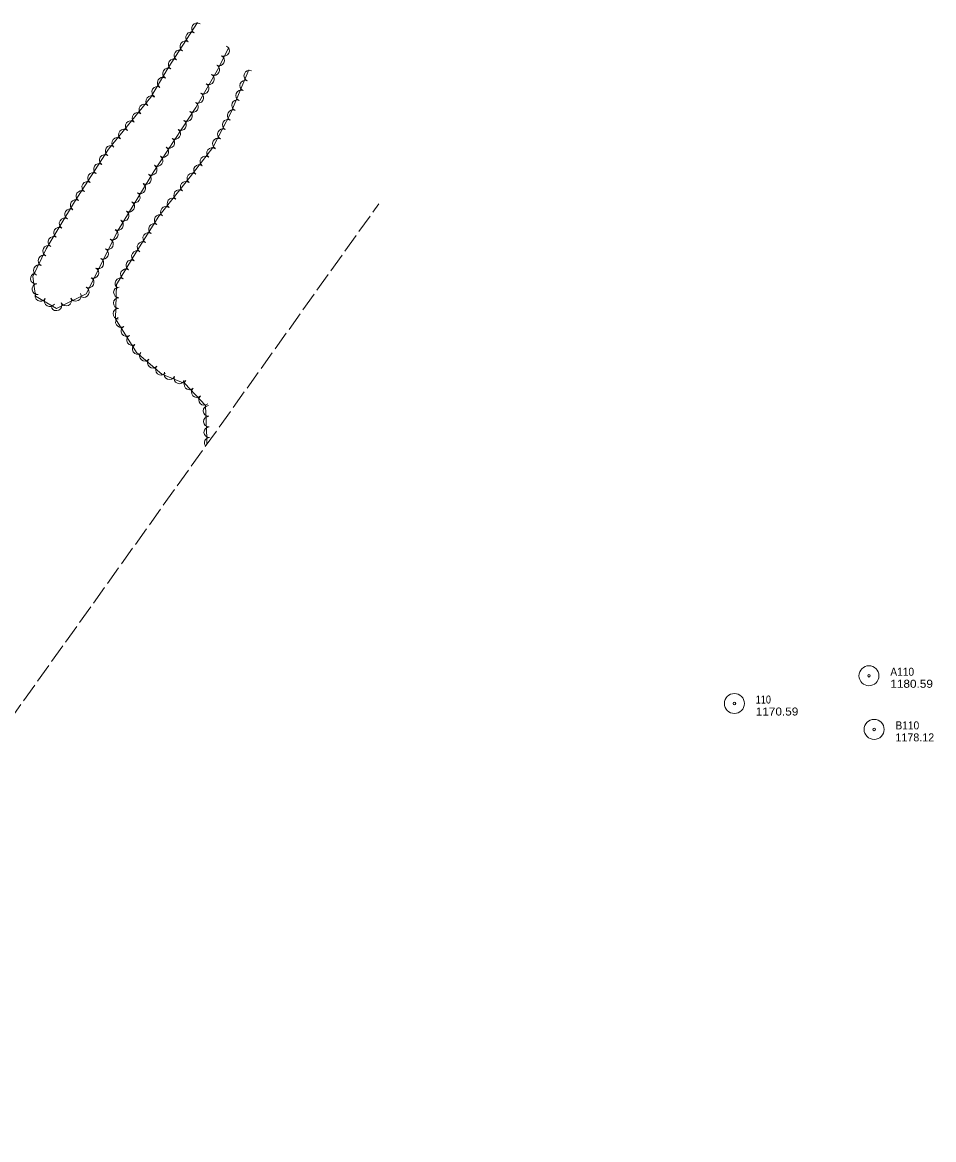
# Model space of a CAD drawing. Extents: x 298072 to 300359, y 47756 to 50122.
# Drawn here: x 299676 to 300359, y 48286 to 49123 of the extents above; entities that cross this region are included whole.
import ezdxf

# ---------------------------------------------------------------- set-up
doc = ezdxf.new("R2010")
doc.units = 0
doc.header["$LTSCALE"] = 2.4
doc.linetypes.add('LONG_DASHED', pattern=[7.5, 6, -1.5])
for name, color, linetype, lineweight in [('18', 7, 'Continuous', 13), ('4', 7, 'Continuous', 13), ('6', 7, 'Continuous', 13)]:
    doc.layers.add(name, color=color, linetype=linetype, lineweight=lineweight)

msp = doc.modelspace()

# ---------------------------------------------------------------- linework, layer by layer
at = {"layer": '18'}
for points in [[(299807.427, 49123.128), (299785.282, 49089.002), (299772.357, 49066.944), (299740.591, 49028.036), (299715.161, 48988.72), (299693.854, 48953.382), (299683.94, 48932.544), (299685.992, 48917.856), (299701.571, 48908.735), (299723.825, 48919.654), (299747.803, 48967.414), (299774.543, 49011.39), (299806.019, 49059.246), (299822.144, 49087.161), (299830.837, 49104.378)], [(299845.727, 49087.598), (299832.328, 49055.349), (299818.687, 49029.29), (299801.791, 49007.312), (299778.25, 48977.779), (299761.263, 48950.809), (299746.548, 48926.585), (299745.914, 48901.043), (299761.679, 48875.802), (299780.701, 48859.42), (299797.834, 48852.383), (299813.404, 48835.916), (299814.228, 48811.396), (299814.385, 48806.967)]]:
    msp.add_lwpolyline(points, dxfattribs=at)
for centre, radius, start, end in [((299807.003, 49118.605), 4.025, 57.02737, 237.01204), ((299798.24, 49105.101), 4.025, 57.02737, 237.01204), ((299802.622, 49111.853), 4.025, 57.02737, 237.01204), ((299793.859, 49098.35), 4.025, 57.02737, 237.01204), ((299827.143, 49101.735), 4.025, 243.21809, 63.20277), ((299789.478, 49091.598), 4.025, 57.02737, 237.01204), ((299823.515, 49094.551), 4.025, 243.21809, 63.20277), ((299785.286, 49084.842), 4.025, 59.63927, 239.62395), ((299815.877, 49080.523), 4.025, 239.99494, 59.97961), ((299819.903, 49087.492), 4.025, 239.99494, 59.97961), ((299846.125, 49083.105), 3.996, 67.44547, 247.43015), ((299781.217, 49077.897), 4.025, 59.63927, 239.62395), ((299811.851, 49073.553), 4.025, 239.99494, 59.97961), ((299843.059, 49075.725), 3.996, 67.44547, 247.43015), ((299772.618, 49063.932), 4.025, 50.77813, 230.76281), ((299777.148, 49070.953), 4.025, 59.63927, 239.62395), ((299807.825, 49066.584), 4.025, 239.99494, 59.97961), ((299839.993, 49068.345), 3.996, 67.44547, 247.43015), ((299767.527, 49057.698), 4.025, 50.77813, 230.76281), ((299803.824, 49059.742), 4.025, 236.67382, 56.65849), ((299836.926, 49060.965), 3.996, 67.44547, 247.43015), ((299762.437, 49051.463), 4.025, 50.77813, 230.76281), ((299799.401, 49053.017), 4.025, 236.67382, 56.65849), ((299829.992, 49046.377), 3.996, 62.37713, 242.36181), ((299833.698, 49053.457), 3.996, 62.37713, 242.36181), ((299752.257, 49038.994), 4.025, 50.77813, 230.76281), ((299757.347, 49045.228), 4.025, 50.77813, 230.76281), ((299790.555, 49039.568), 4.025, 236.67382, 56.65849), ((299794.978, 49046.293), 4.025, 236.67382, 56.65849), ((299826.286, 49039.296), 3.996, 62.37713, 242.36181), ((299747.166, 49032.759), 4.025, 50.77813, 230.76281), ((299786.132, 49032.843), 4.025, 236.67382, 56.65849), ((299822.58, 49032.216), 3.996, 62.37713, 242.36181), ((299742.234, 49026.697), 4.025, 57.11245, 237.09713), ((299781.709, 49026.119), 4.025, 236.67382, 56.65849), ((299818.155, 49025.166), 3.996, 52.4557, 232.44038), ((299733.491, 49013.181), 4.025, 57.11245, 237.09713), ((299737.862, 49019.939), 4.025, 57.11245, 237.09713), ((299777.286, 49019.394), 4.025, 236.67382, 56.65849), ((299808.413, 49012.495), 3.996, 52.4557, 232.44038), ((299813.284, 49018.83), 3.996, 52.4557, 232.44038), ((299729.12, 49006.422), 4.025, 57.11245, 237.09713), ((299768.637, 49005.732), 4.025, 238.70559, 58.69027), ((299772.863, 49012.67), 4.025, 236.67382, 56.65849), ((299803.543, 49006.159), 3.996, 52.4557, 232.44038), ((299724.748, 48999.664), 4.025, 57.11245, 237.09713), ((299764.455, 48998.855), 4.025, 238.70559, 58.69027), ((299798.541, 48999.879), 3.996, 51.44902, 231.4337), ((299720.377, 48992.906), 4.025, 57.11245, 237.09713), ((299760.274, 48991.978), 4.025, 238.70559, 58.69027), ((299788.578, 48987.381), 3.996, 51.44902, 231.4337), ((299793.56, 48993.63), 3.996, 51.44902, 231.4337), ((299711.931, 48979.283), 4.025, 58.91984, 238.90452), ((299716.087, 48986.175), 4.025, 58.91984, 238.90452), ((299756.092, 48985.1), 4.025, 238.70559, 58.69027), ((299783.597, 48981.131), 3.996, 51.44902, 231.4337), ((299707.775, 48972.39), 4.025, 58.91984, 238.90452), ((299747.728, 48971.346), 4.025, 238.70559, 58.69027), ((299751.91, 48978.223), 4.025, 238.70559, 58.69027), ((299778.934, 48974.94), 3.996, 57.80297, 237.78765), ((299703.619, 48965.497), 4.025, 58.91984, 238.90452), ((299743.799, 48964.134), 4.025, 243.34863, 63.33331), ((299774.675, 48968.178), 3.996, 57.80297, 237.78765), ((299699.463, 48958.604), 4.025, 58.91984, 238.90452), ((299740.188, 48956.941), 4.025, 243.34863, 63.33331), ((299766.157, 48954.654), 3.996, 57.80297, 237.78765), ((299770.416, 48961.416), 3.996, 57.80297, 237.78765), ((299695.464, 48951.862), 4.025, 64.56417, 244.54885), ((299736.576, 48949.748), 4.025, 243.34863, 63.33331), ((299761.945, 48947.903), 3.996, 58.73085, 238.71553), ((299688.548, 48937.326), 4.025, 64.56417, 244.54885), ((299692.006, 48944.594), 4.025, 64.56417, 244.54885), ((299732.965, 48942.555), 4.025, 243.34863, 63.33331), ((299757.796, 48941.073), 3.996, 58.73085, 238.71553), ((299686.269, 48931.101), 4.025, 97.96074, 277.94542), ((299729.354, 48935.361), 4.025, 243.34863, 63.33331), ((299753.647, 48934.242), 3.996, 58.73085, 238.71553), ((299687.382, 48923.13), 4.025, 97.96074, 277.94542), ((299722.131, 48920.975), 4.025, 243.34863, 63.33331), ((299725.742, 48928.168), 4.025, 243.34863, 63.33331), ((299748.496, 48920.782), 3.996, 88.58577, 268.57044), ((299749.498, 48927.412), 3.996, 58.73085, 238.71553), ((299689.661, 48918.149), 4.025, 149.66007, 329.64475), ((299696.607, 48914.083), 4.025, 149.66007, 329.64475), ((299708.823, 48914.64), 4.025, 206.14269, 26.12737), ((299716.049, 48918.185), 4.025, 206.14269, 26.12737), ((299748.298, 48912.793), 3.996, 88.58577, 268.57044), ((299701.597, 48911.094), 4.025, 206.14269, 26.12737), ((299748.1, 48904.804), 3.996, 88.58577, 268.57044), ((299749.901, 48898.607), 3.996, 121.9957, 301.98038), ((299754.135, 48891.829), 3.996, 121.9957, 301.98038), ((299758.368, 48885.051), 3.996, 121.9957, 301.98038), ((299762.602, 48878.273), 3.996, 121.9957, 301.98038), ((299767.882, 48873.221), 3.996, 139.27219, 319.25687), ((299773.937, 48868.005), 3.996, 139.27219, 319.25687), ((299779.993, 48862.79), 3.996, 139.27219, 319.25687), ((299786.357, 48859.358), 3.996, 157.67834, 337.66302), ((299793.749, 48856.322), 3.996, 157.67834, 337.66302), ((299801.22, 48851.846), 3.996, 133.40386, 313.38854), ((299806.711, 48846.039), 3.996, 133.40386, 313.38854), ((299812.201, 48840.232), 3.996, 133.40386, 313.38854), ((299815.63, 48831.959), 3.996, 91.93237, 271.91705), ((299815.898, 48823.972), 3.996, 91.93237, 271.91705), ((299816.167, 48815.985), 3.996, 91.93237, 271.91705), ((299816.441, 48808.002), 3.996, 92.03223, 218.9084)]:
    msp.add_arc(centre, radius, start, end, dxfattribs=at)
at = {"layer": '4', "linetype": 'LONG_DASHED'}
msp.add_line((299321.306, 48116.776), (299943.155, 48987.214), dxfattribs=at)
at = {"layer": '6'}
for centre, radius in [((300310.324, 48633.457), 7.5), ((300310.324, 48633.457), 0.96), ((300209.513, 48612.655), 7.5), ((300209.513, 48612.655), 0.96), ((300314.174, 48593.267), 7.5), ((300314.174, 48593.267), 0.96)]:
    msp.add_circle(centre, radius, dxfattribs=at)

# ---------------------------------------------------------------- texts
for s, width, p in [('A110', 0.95, (300326.324, 48633.457)), ('1180.59', 1.1, (300326.324, 48624.457)), ('110', 0.85, (300225.513, 48612.655)), ('1170.59', 1.1, (300225.513, 48603.655)), ('B110', 0.95, (300330.174, 48593.267))]:
    msp.add_text(s, height=6, dxfattribs=dict(at, width=width)).set_placement(p)
msp.add_text('1178.12', height=6, dxfattribs=at).set_placement((300330.174, 48584.267))

doc.saveas('drawing.dxf')
